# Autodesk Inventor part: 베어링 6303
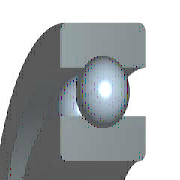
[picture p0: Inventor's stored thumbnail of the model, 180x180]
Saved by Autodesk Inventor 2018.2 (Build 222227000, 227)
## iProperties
IsCustomPart: 1
Created: 2012-02
Part Number: 베어링 6303
Material: 강철, 연강
Description: 단열 볼 베어링
Document SubType Name: Modeling
Standard: JIS B 1521
Designer: mdu-01
Standards Organization: JIS
Language: ko-KR
Size Designation: SKF 6303
Categories: <MemberInstance><Categories><Category DisplayName="샤프트 부품" InternalName="7f7aeb1f-a693-4053-b835-cee3144e0d98" Mnemonic="SHFT"><Category DisplayName="베어링" Inter
Density: 7.86 g/cm^3
Mass: 109.207 g
Surface Area: 91.3626 cm^2
Volume: 13.894 cm^3
Appearance: 노란색
Author: mdu-01
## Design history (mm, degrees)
node "WorkPoint1"
node "WorkAxis1"
node "WorkPlane3"
node "WorkPlane4"
node "WorkPoint2"
body "Solid1"
node "스케치1"
revolve "회전1" stored, may be unused: angle "d6" = 360 deg
revolve "회전2" stored, may be unused: angle "d10" = 360 deg
node "스케치4"
revolve "회전3" stored, may be unused: angle "d16" = 360 deg
pattern_circular "원형 배열1" dims "d17" = 57.33333 (= msp_pocet), angle "d19" = 360 deg
fillet "모깎기1" dims "d20" = 1 (= r)
sketch "스케치2"
  geometry: L1 (8.5, 14)-(23.5, 14); L2 (8.5, 0)-(8.5, 14); L3 (23.5, 0)-(8.5, 0); L4 (23.5, 14)-(23.5, 0); L5 (0, 0)-(0, 20); L6 (0, 0)-(0, 20); L7 (-7.2, 0)-(43.2, 0) reference
  constraints: 12 end point, 3 vertical, 2 horizontal, 1 collinear, 1 other
  dimensions: "d1" = 17 diameter of L1.start L5 (= Diam); "d3" = 47 diameter of L1.end L5 (= DD); "d5" = 14 distance of L2.start L1.start (= msp_mdtd2)
sketch "스케치3"
  geometry: L1 (18.7, 14)-(18.7, 10.6); L2 (13.3, 14)-(18.7, 14); L3 (13.3, 10.6)-(13.3, 14); L4 (13.3, 0)-(13.3, 3.4); L5 (18.7, 0)-(13.3, 0); L6 (18.7, 3.4)-(18.7, 0); L7 (23.5, 0)-(-23.5, 0) reference; L8 (23.5, 14)-(-23.5, 14) reference; L9 (0, -42.29)-(0, 61.29); L10 (0, 82.007)-(0, -63.007) reference; A1 r 4.5 centre (16, 7) between (18.7, 3.4) and (18.7, 10.6); A2 r 4.5 centre (16, 7) between (13.3, 10.6) and (13.3, 3.4)
  constraints: 14 end point, 4 collinear, 4 point on circle, 4 vertical, 2 centre point, 2 concentric, 2 horizontal, 2 point on line
  dimensions: "d9" = 9 diameter of A1 (= msp_mdtd6); "d21" = 13.3 distance between parallel lines of L9 L4 (= 0.5 x msp_d1); "d22" = 16 distance from line of L9 A1.centre (= 0.5 x msp_ds); "d23" = 18.7 distance between parallel lines of L9 L6 (= 0.5 x msp_dd1)
sketch "스케치5"
  geometry: L1 (16, 2.5)-(16, 11.5); L2 (18.7, 0)-(-18.7, 0) reference; L3 (16, 2.5)-(16, 11.5); A1 r 4.5 centre (16, 7) between (16, 2.5) and (16, 11.5); A2 r 4.5 centre (16, 7) between (18.7, 3.4) and (18.7, 10.6) reference
  constraints: 4 end point, 2 point on circle, 1 centre point, 1 concentric, 1 vertical
  dimensions: "d13" = 0 horizontal distance of A1.centre L1.start; "d15" = 9.0001 diameter of A1 (computed from msp_mdtd6)
other parameters: "Diam" = 17 [user parameter; used in 3 equation terms], "DD" = 47 [user parameter; used in 3 equation terms], "B" = 14 [user parameter; used in 1 equation term], "r" = 1 [user parameter; used in 1 equation term], "msp_ds" = 32 (= 0.5 x Diam + 0.5 x DD) [user parameter; used in 5 equation terms], "msp_d0" = 9 (= -0.3 x Diam + 0.3 x DD) [user parameter; used in 4 equation terms], "msp_d1" = 26.6 (= msp_ds - 0.6 x msp_d0) [user parameter; used in 1 equation term], "msp_dd1" = 37.4 (= msp_ds + 0.6 x msp_d0) [user parameter; used in 1 equation term], "msp_pom" = 48 (= 1.5 x msp_ds) [user parameter; used in 1 equation term], "msp_mdtd2" = 14 (= B) [user parameter; used in 3 equation terms], "msp_mdtd4" = 32 (= msp_ds) [user parameter], "msp_mdtd6" = 9 (= msp_d0) [user parameter; used in 2 equation terms], "msp_mdtd7" = 7 (= 0.5 x msp_mdtd2) [user parameter], "msp_pocet" = 57.33333 (computed from msp_d0, msp_pom) [user parameter; used in 1 equation term], "d2" = 72 (derived), "d4" = 19 (derived), "d7" = 0, "d8" = 15.6 (derived), "d11" = -14 (computed from msp_mdtd2), "d12" = 0 (derived), "d14" = 15.6001 (derived), "d26" = 0, "d27" = 0, "d28" = 0, "d29" = 0, "d30" = 0
